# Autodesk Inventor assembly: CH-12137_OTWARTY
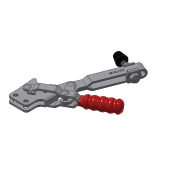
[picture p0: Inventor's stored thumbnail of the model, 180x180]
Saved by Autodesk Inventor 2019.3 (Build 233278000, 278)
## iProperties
Company: Î¢ÈíÖÐ¹ú
Created: 2012-09
Part Number: CH-12137_OTWARTY
Material: Ogólny
Description: STEP AP203
Document SubType Name: Assembly
Designer: CADENGINEERING4
Sending System: SolidWorks 2010
Preprocessor: SwSTEP 2.0
Title: CH-12137.STEP
Author: Î¢ÈíÓÃ»§
Revision Number: ÈÎºÎ
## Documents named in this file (12)
- D:\Vault_2016\Projekty\NASZ KATALOG\CLAMPTEK\STRONA\Vertical toggle clamp\CH-12137\CH-12137_OTWARTY.iam
- D:\Vault_2016\Projekty\NASZ KATALOG\CLAMPTEK\STEP FILES\Vertical toggle clamp\CH-12137\CH-FC-56212 SPINDLE SUPPLIED.ipt
- D:\Vault_2016\Projekty\NASZ KATALOG\CLAMPTEK\STEP FILES\Vertical toggle clamp\CH-12137\CH-12130-05.ipt
- D:\Vault_2016\Projekty\NASZ KATALOG\CLAMPTEK\STEP FILES\Vertical toggle clamp\CH-12137\CH-12130-07.ipt
- D:\Vault_2016\Projekty\NASZ KATALOG\CLAMPTEK\STEP FILES\Vertical toggle clamp\CH-12137\CH-12130-06.ipt
- D:\Vault_2016\Projekty\NASZ KATALOG\CLAMPTEK\STEP FILES\Vertical toggle clamp\CH-12137\CH-12145-01 STRAIGHT BASE.ipt
- D:\Vault_2016\Projekty\NASZ KATALOG\CLAMPTEK\STEP FILES\Vertical toggle clamp\CH-12137\CH-FC-56212 Nut.ipt
- D:\Vault_2016\Projekty\NASZ KATALOG\CLAMPTEK\STEP FILES\Vertical toggle clamp\CH-12137\CH-FW-516.ipt
- D:\Vault_2016\Projekty\NASZ KATALOG\CLAMPTEK\STEP FILES\Vertical toggle clamp\CH-12137\CH-12130-04 CONNECTING-PLATE.ipt
- D:\Vault_2016\Projekty\NASZ KATALOG\CLAMPTEK\STEP FILES\Vertical toggle clamp\CH-12137\CH-12137-02 LONG U-BAR.ipt
- D:\Vault_2016\Projekty\NASZ KATALOG\CLAMPTEK\STEP FILES\Vertical toggle clamp\CH-12137\CH-12130-08.ipt
- D:\Vault_2016\Projekty\NASZ KATALOG\CLAMPTEK\STEP FILES\Vertical toggle clamp\CH-12137\CH-12130-03 STRAIGHT HANDLE.ipt
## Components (15 placed, 11 different names)
1. CH-12145-01 STRAIGHT BASE_6
2. CH-FC-56212 SPINDLE SUPPLIED:2 — Zestawiające:19, Równoległe:2
3. CH-12130-05:2 — Zestawiające:1, Równoległe:1
4. CH-12130-07:2 — Zestawiające:16, Zestawiające:17, Zestawiające:18
5. CH-12130-06:3 — Zestawiające:5, Zestawiające:6, Zestawiające:7, Zestawiające:8, Zestawiające:9
6. CH-12130-06:4 — Zestawiające:29, Zestawiające:30
7. CH-FC-56212 Nut:3 — Zestawiające:21, Zestawiające:22, Zestawiające:25, Zestawiające:27, Zestawiające:28
8. CH-FW-516:3 — Zestawiające:20, Zestawiające:24, Zestawiające:26, Równoległe:3
9. CH-12130-04 CONNECTING-PLATE:2 — Zestawiające:5, Zestawiające:7, Zestawiające:8, Zestawiające:9, Zestawiające:10, Zestawiające:11, Zestawiające:13, Zestawiające:14, Zestawiające:30
10. CH-12137-02 LONG U-BAR:2 — Równoległe:1, Zestawiające:6, Zestawiające:10, Zestawiające:23, Zestawiające:24, Równoległe:2, Zestawiające:27, Zestawiające:28, Zestawiające:29, Kątowe:1
11. CH-FW-516:4 — Zestawiające:22, Zestawiające:23, Zestawiające:25, Równoległe:3, Kątowe:1
12. CH-12130-08:3 — Zestawiające:1, Zestawiające:2, Zestawiające:3, Zestawiające:4
13. CH-FC-56212 Nut:4 — Zestawiające:19, Zestawiające:20, Zestawiające:21, Zestawiające:26
14. CH-12130-03 STRAIGHT HANDLE:2 — Zestawiające:2, Zestawiające:3, Zestawiające:4, Zestawiające:11, Zestawiające:12, Zestawiające:15, Zestawiające:16, Zestawiające:17, Zestawiające:18, Zestawiające:33
15. CH-12130-08:4 — Zestawiające:12, Zestawiające:13, Zestawiające:14, Zestawiające:15, Zestawiające:33
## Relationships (35: Mate 31, Flush 3, Angle 1)
- Zestawiające:1 [Mate]: CH-12130-05:2 ↔ CH-12130-08:3
- Zestawiające:2 [Mate]: CH-12130-08:3 ↔ CH-12130-03 STRAIGHT HANDLE:2
- Zestawiające:3 [Mate]: CH-12130-08:3 ↔ CH-12130-03 STRAIGHT HANDLE:2
- Zestawiające:4 [Mate]: CH-12130-08:3 ↔ CH-12130-03 STRAIGHT HANDLE:2
- Równoległe:1 [Flush]: CH-12130-05:2 ↔ CH-12137-02 LONG U-BAR:2
- Zestawiające:5 [Mate]: CH-12130-06:3 ↔ CH-12130-04 CONNECTING-PLATE:2
- Zestawiające:6 [Mate]: CH-12130-06:3 ↔ CH-12137-02 LONG U-BAR:2
- Zestawiające:7 [Mate]: CH-12130-06:3 ↔ CH-12130-04 CONNECTING-PLATE:2
- Zestawiające:8 [Mate]: CH-12130-06:3 ↔ CH-12130-04 CONNECTING-PLATE:2
- Zestawiające:9 [Mate]: CH-12130-06:3 ↔ CH-12130-04 CONNECTING-PLATE:2
- Zestawiające:10 [Mate]: CH-12130-04 CONNECTING-PLATE:2 ↔ CH-12137-02 LONG U-BAR:2
- Zestawiające:11 [Mate]: CH-12130-04 CONNECTING-PLATE:2 ↔ CH-12130-03 STRAIGHT HANDLE:2
- Zestawiające:12 [Mate]: CH-12130-03 STRAIGHT HANDLE:2 ↔ CH-12130-08:4
- Zestawiające:13 [Mate]: CH-12130-04 CONNECTING-PLATE:2 ↔ CH-12130-08:4
- Zestawiające:14 [Mate]: CH-12130-04 CONNECTING-PLATE:2 ↔ CH-12130-08:4
- Zestawiające:15 [Mate]: CH-12130-03 STRAIGHT HANDLE:2 ↔ CH-12130-08:4
- Zestawiające:16 [Mate]: CH-12130-07:2 ↔ CH-12130-03 STRAIGHT HANDLE:2
- Zestawiające:17 [Mate]: CH-12130-07:2 ↔ CH-12130-03 STRAIGHT HANDLE:2
- Zestawiające:18 [Mate]: CH-12130-07:2 ↔ CH-12130-03 STRAIGHT HANDLE:2
- Zestawiające:19 [Mate]: CH-FC-56212 SPINDLE SUPPLIED:2 ↔ CH-FC-56212 Nut:4
- Zestawiające:20 [Mate]: CH-FW-516:3 ↔ CH-FC-56212 Nut:4
- Zestawiające:21 [Mate]: CH-FC-56212 Nut:3 ↔ CH-FC-56212 Nut:4
- Zestawiające:22 [Mate]: CH-FC-56212 Nut:3 ↔ CH-FW-516:4
- Zestawiające:23 [Mate]: CH-12137-02 LONG U-BAR:2 ↔ CH-FW-516:4
- Zestawiające:24 [Mate]: CH-FW-516:3 ↔ CH-12137-02 LONG U-BAR:2
- Zestawiające:25 [Mate]: CH-FC-56212 Nut:3 ↔ CH-FW-516:4
- Zestawiające:26 [Mate]: CH-FW-516:3 ↔ CH-FC-56212 Nut:4
- Równoległe:2 [Flush]: CH-FC-56212 SPINDLE SUPPLIED:2 ↔ CH-12137-02 LONG U-BAR:2
- Zestawiające:27 [Mate]: CH-FC-56212 Nut:3 ↔ CH-12137-02 LONG U-BAR:2
- Zestawiające:28 [Mate]: CH-FC-56212 Nut:3 ↔ CH-12137-02 LONG U-BAR:2
- Zestawiające:29 [Mate]: CH-12130-06:4 ↔ CH-12137-02 LONG U-BAR:2
- Zestawiające:30 [Mate]: CH-12130-06:4 ↔ CH-12130-04 CONNECTING-PLATE:2
- Zestawiające:33 [Mate]: CH-12130-03 STRAIGHT HANDLE:2 ↔ CH-12130-08:4
- Równoległe:3 [Flush]: CH-FW-516:3 ↔ CH-FW-516:4
- Kątowe:1 [Angle]: CH-12137-02 LONG U-BAR:2 ↔ CH-FW-516:4
